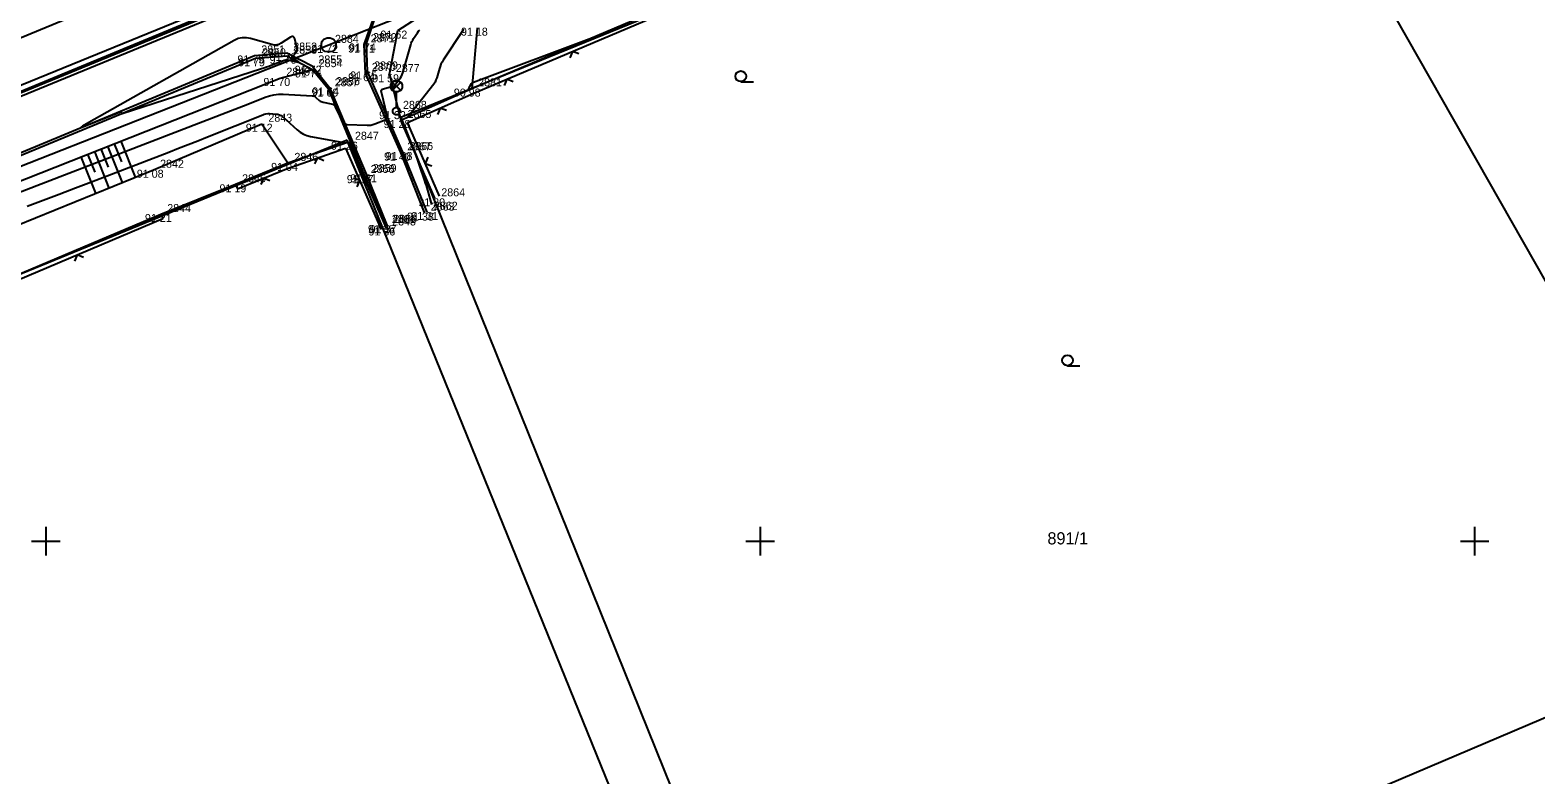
# Model space of a CAD drawing. Extents: x -711081 to -709338, y -1025122 to -1024092.
# Drawn here: x -710150.5 to -710097.9, y -1024708.2 to -1024682.1 of the extents above; entities that cross this region are included whole.
import ezdxf

# ---------------------------------------------------------------- set-up
doc = ezdxf.new("R2010")
doc.units = 0
for name, color, linetype in [('Ex_Major Contours', 7, 'Continuous'), ('Ex_Minor Contours', 7, 'Continuous'), ('Z_body', 7, 'Continuous'), ('Z_body_cisla', 7, 'Continuous'), ('Z_body_vysky_redukovane', 7, 'Continuous'), ('Z_chodnik', 7, 'Continuous'), ('Z_hektometricka_sit', 7, 'Continuous'), ('Z_hrany_paty', 7, 'Continuous'), ('Z_katastr_cisla_pozemkova', 7, 'Continuous'), ('Z_katastr_hranice', 7, 'Continuous'), ('Z_katastr_znacky_kultur', 7, 'Continuous'), ('Z_komunikace', 7, 'Continuous'), ('Z_obruba', 7, 'Continuous'), ('Z_ploty', 7, 'Continuous'), ('Z_ploty_znacky', 7, 'Continuous'), ('Z_site_kanalizace_znaky', 7, 'Continuous'), ('Z_site_vo_znaky', 7, 'Continuous'), ('Z_technicke_srafy', 7, 'Continuous'), ('Z_vdz12_plna', 7, 'Continuous'), ('Z_vdz25_plna', 7, 'Continuous'), ('Z_vstupy', 7, 'Continuous'), ('Z_znaky_kultur', 7, 'Continuous')]:
    doc.layers.add(name, color=color, linetype=linetype)

# ---------------------------------------------------------------- blocks, each defined once
blk = doc.blocks.new('POINT_DISPLAY')
blk.add_line((0, 0), (0, 0))
blk = doc.blocks.new('Z212')
for p, q in [((-0.17, 0.17), (0, 0)), ((0, 0), (0.17, 0.17))]:
    blk.add_line(p, q)
blk = doc.blocks.new('Z34')
for p, q in [((-0.15, 1.02), (-0.05, 1.07)), ((-0.05, 1.07), (0.05, 1.07)), ((0.05, 1.07), (0.15, 1.02)), ((-0.2, 0.93), (-0.15, 1.02)), ((-0.2, 0.82), (-0.2, 0.93)), ((-0.15, 0.72), (-0.2, 0.82)), ((0.15, 0.72), (-0.15, 1.02)), ((0.15, 1.02), (-0.15, 0.72)), ((-0.05, 0.68), (-0.15, 0.72)), ((0.05, 0.68), (-0.05, 0.68)), ((0, 0.13), (0, 0.68)), ((0.15, 0.72), (0.05, 0.68)), ((0.15, 1.02), (0.2, 0.93)), ((0.2, 0.82), (0.15, 0.72)), ((0.2, 0.93), (0.2, 0.82)), ((-0.13, 0.03), (-0.1, 0.08)), ((-0.13, -0.03), (-0.13, 0.03)), ((-0.1, 0.08), (-0.08, 0.1)), ((-0.08, 0.1), (-0.03, 0.13)), ((-0.03, 0.13), (0.03, 0.13)), ((0.03, 0.13), (0.08, 0.1)), ((0.08, 0.1), (0.1, 0.08)), ((0.1, 0.08), (0.13, 0.03)), ((0.13, 0.03), (0.13, -0.03)), ((-0.1, -0.08), (-0.13, -0.03)), ((-0.08, -0.1), (-0.1, -0.08)), ((-0.03, -0.13), (-0.08, -0.1)), ((0.03, -0.13), (-0.03, -0.13)), ((0.08, -0.1), (0.03, -0.13)), ((0.1, -0.08), (0.08, -0.1)), ((0.13, -0.03), (0.1, -0.08))]:
    blk.add_line(p, q)
blk = doc.blocks.new('Z620')
for p, q in [((-0.25, 0.05), (-0.23, 0.13)), ((-0.25, -0.05), (-0.25, 0.05)), ((-0.23, 0.13), (-0.17, 0.2)), ((-0.17, 0.2), (-0.05, 0.25)), ((-0.05, 0.25), (0.05, 0.25)), ((0.05, 0.25), (0.17, 0.2)), ((0.17, 0.2), (0.23, 0.13)), ((0.23, 0.13), (0.25, 0.05)), ((0.25, 0.05), (0.25, -0.05)), ((-0.2, -0.17), (-0.25, -0.05)), ((-0.13, -0.23), (-0.2, -0.17)), ((-0.05, -0.25), (-0.13, -0.23)), ((0.05, -0.25), (-0.05, -0.25)), ((0.13, -0.23), (0.05, -0.25)), ((0.2, -0.17), (0.13, -0.23)), ((0.25, -0.05), (0.2, -0.17))]:
    blk.add_line(p, q)
blk = doc.blocks.new('Z304')
blk.add_line((0, -0.19), (0.44, -0.19))
blk.add_circle((0, 0), 0.188)

msp = doc.modelspace()

# ---------------------------------------------------------------- linework, layer by layer
at = {"layer": 'Ex_Major Contours'}
msp.add_lwpolyline([(-710135.255, -1024684.233), (-710135.192, -1024684.153), (-710135.188, -1024684.148), (-710135.185, -1024684.143), (-710135.183, -1024684.138), (-710135.181, -1024684.132), (-710135.174, -1024684.108), (-710135.172, -1024684.103), (-710135.17, -1024684.097), (-710135.167, -1024684.092), (-710135.164, -1024684.086), (-710135.097, -1024683.984), (-710135.083, -1024683.967), (-710135.068, -1024683.952), (-710135.05, -1024683.94), (-710135.03, -1024683.931), (-710130.89, -1024682.38)], dxfattribs=at)
at = {"layer": 'Ex_Minor Contours'}
for points in [[(-710153.747, -1024688.868), (-710143.533, -1024684.942), (-710143.381, -1024684.884), (-710143.229, -1024684.824), (-710143.078, -1024684.765), (-710142.927, -1024684.705), (-710142.323, -1024684.463), (-710142.17, -1024684.411), (-710142.015, -1024684.376), (-710141.857, -1024684.359), (-710141.696, -1024684.359), (-710140.681, -1024684.412), (-710140.643, -1024684.417), (-710140.608, -1024684.428), (-710140.576, -1024684.445), (-710140.545, -1024684.468), (-710140.43, -1024684.572), (-710140.4, -1024684.596), (-710140.367, -1024684.615), (-710140.332, -1024684.629), (-710140.295, -1024684.638), (-710140.012, -1024684.689), (-710139.965, -1024684.703), (-710139.926, -1024684.726), (-710139.893, -1024684.758), (-710139.868, -1024684.8), (-710139.753, -1024685.047), (-710139.745, -1024685.062), (-710139.737, -1024685.078), (-710139.728, -1024685.093), (-710139.719, -1024685.107), (-710139.681, -1024685.165), (-710139.671, -1024685.18), (-710139.662, -1024685.195), (-710139.652, -1024685.209), (-710139.643, -1024685.224), (-710139.561, -1024685.356), (-710139.542, -1024685.38), (-710139.52, -1024685.397), (-710139.493, -1024685.408), (-710139.464, -1024685.413), (-710138.759, -1024685.444), (-710138.689, -1024685.443), (-710138.62, -1024685.435), (-710138.552, -1024685.42), (-710138.486, -1024685.398), (-710138.124, -1024685.254), (-710138.11, -1024685.247), (-710138.101, -1024685.236), (-710138.096, -1024685.223), (-710138.096, -1024685.208), (-710138.103, -1024685.12), (-710138.103, -1024685.115), (-710138.101, -1024685.111), (-710138.097, -1024685.11), (-710138.091, -1024685.111), (-710138.064, -1024685.122), (-710138.059, -1024685.123), (-710138.055, -1024685.122), (-710138.054, -1024685.119), (-710138.055, -1024685.113), (-710138.257, -1024684.29), (-710138.261, -1024684.245), (-710138.25, -1024684.21), (-710138.224, -1024684.184), (-710138.183, -1024684.166), (-710137.902, -1024684.093), (-710137.896, -1024684.092), (-710137.891, -1024684.093), (-710137.886, -1024684.095), (-710137.881, -1024684.099), (-710137.863, -1024684.116), (-710137.858, -1024684.119), (-710137.854, -1024684.12), (-710137.85, -1024684.118), (-710137.846, -1024684.115), (-710137.622, -1024683.831), (-710137.586, -1024683.781), (-710137.556, -1024683.728), (-710137.531, -1024683.673), (-710137.511, -1024683.614), (-710137.228, -1024682.628), (-710137.209, -1024682.57), (-710137.186, -1024682.515), (-710137.159, -1024682.461), (-710137.127, -1024682.409), (-710136.992, -1024682.205), (-710136.956, -1024682.156), (-710136.915, -1024682.113)], [(-710135.376, -1024682.09), (-710135.406, -1024682.13), (-710136.092, -1024683.166), (-710136.134, -1024683.236), (-710136.171, -1024683.309), (-710136.203, -1024683.384), (-710136.228, -1024683.462), (-710136.319, -1024683.78), (-710136.346, -1024683.857), (-710136.379, -1024683.931), (-710136.42, -1024684.002), (-710136.467, -1024684.068), (-710137.322, -1024685.15)], [(-710150.656, -1024688.277), (-710150.091, -1024688.064), (-710149.526, -1024687.851), (-710148.961, -1024687.636), (-710148.398, -1024687.42), (-710145.699, -1024686.383), (-710145.357, -1024686.251), (-710145.016, -1024686.117), (-710144.676, -1024685.983), (-710144.336, -1024685.848), (-710142.409, -1024685.076), (-710142.352, -1024685.057), (-710142.294, -1024685.044), (-710142.235, -1024685.038), (-710142.175, -1024685.038), (-710141.933, -1024685.051), (-710141.874, -1024685.058), (-710141.819, -1024685.076), (-710141.768, -1024685.102), (-710141.721, -1024685.138), (-710141.204, -1024685.603), (-710141.098, -1024685.686), (-710140.985, -1024685.752), (-710140.863, -1024685.801), (-710140.733, -1024685.833), (-710139.506, -1024686.054)], [(-710137.124, -1024686.288), (-710136.747, -1024687.386), (-710136.72, -1024687.468), (-710136.693, -1024687.551), (-710136.668, -1024687.634), (-710136.644, -1024687.717), (-710136.503, -1024688.218)]]:
    msp.add_lwpolyline(points, dxfattribs=at)
msp.add_lwpolyline([(-710141.842, -1024682.613), (-710141.92, -1024682.634), (-710142.002, -1024682.636), (-710142.086, -1024682.621), (-710142.83, -1024682.408), (-710142.98, -1024682.379), (-710143.127, -1024682.381), (-710143.271, -1024682.413), (-710143.411, -1024682.476), (-710148.58, -1024685.39), (-710148.718, -1024685.472), (-710148.76, -1024685.508), (-710148.706, -1024685.498), (-710148.555, -1024685.442), (-710147.379, -1024684.973), (-710147.372, -1024684.971), (-710147.366, -1024684.972), (-710147.362, -1024684.976), (-710147.358, -1024684.983), (-710147.348, -1024685.017), (-710147.345, -1024685.024), (-710147.34, -1024685.028), (-710147.334, -1024685.029), (-710147.327, -1024685.028), (-710142.451, -1024683.462), (-710142.365, -1024683.434), (-710142.279, -1024683.404), (-710142.193, -1024683.373), (-710142.108, -1024683.34), (-710141.716, -1024683.186), (-710141.658, -1024683.167), (-710141.599, -1024683.158), (-710141.539, -1024683.158), (-710141.479, -1024683.168), (-710141.181, -1024683.235), (-710141.156, -1024683.239), (-710141.146, -1024683.237), (-710141.151, -1024683.228), (-710141.171, -1024683.212), (-710141.324, -1024683.108), (-710141.331, -1024683.102), (-710141.336, -1024683.095), (-710141.339, -1024683.088), (-710141.34, -1024683.079), (-710141.34, -1024683.041), (-710141.339, -1024683.032), (-710141.337, -1024683.024), (-710141.333, -1024683.015), (-710141.328, -1024683.008), (-710141.231, -1024682.886), (-710141.216, -1024682.862), (-710141.207, -1024682.837), (-710141.204, -1024682.811), (-710141.208, -1024682.783), (-710141.286, -1024682.425), (-710141.307, -1024682.369), (-710141.339, -1024682.34), (-710141.382, -1024682.338), (-710141.436, -1024682.363), (-710141.765, -1024682.574)], close=True, dxfattribs=at)
at = {"layer": 'Z_chodnik'}
for p, q in [((-710138.86, -1024682.62), (-710138.51, -1024681.65)), ((-710138.81, -1024683.62), (-710138.86, -1024682.62)), ((-710156.78, -1024688.85), (-710142.69, -1024683)), ((-710142.69, -1024683), (-710141.56, -1024682.91)), ((-710141.56, -1024682.91), (-710140.68, -1024683.36)), ((-710140.68, -1024683.36), (-710140.07, -1024684.12)), ((-710137.58, -1024686.4), (-710138.81, -1024683.62)), ((-710140.07, -1024684.12), (-710138.79, -1024687.16)), ((-710136.75, -1024688.5), (-710137.58, -1024686.4)), ((-710138.79, -1024687.16), (-710138.06, -1024688.94))]:
    msp.add_line(p, q, dxfattribs=at)
at = {"layer": 'Z_hektometricka_sit'}
for p, q in [((-710150, -1024699.5), (-710150, -1024700.5)), ((-710125, -1024699.5), (-710125, -1024700.5)), ((-710100, -1024699.5), (-710100, -1024700.5)), ((-710150.5, -1024700), (-710149.5, -1024700)), ((-710125.5, -1024700), (-710124.5, -1024700)), ((-710100.5, -1024700), (-710099.5, -1024700))]:
    msp.add_line(p, q, dxfattribs=at)
at = {"layer": 'Z_hrany_paty'}
for p, q in [((-710137.68, -1024682.13), (-710135.55, -1024680.75)), ((-710137.97, -1024683.66), (-710137.68, -1024682.13)), ((-710134.91, -1024682.03), (-710135.09, -1024684.16)), ((-710156.89, -1024689.76), (-710141.8, -1024683.79)), ((-710141.8, -1024683.79), (-710140.67, -1024683.49)), ((-710137.97, -1024683.66), (-710137.57, -1024685.26)), ((-710146.23, -1024687), (-710142.44, -1024685.39)), ((-710142.44, -1024685.39), (-710141.53, -1024686.76)), ((-710156.79, -1024691.29), (-710146.23, -1024687))]:
    msp.add_line(p, q, dxfattribs=at)
at = {"layer": 'Z_katastr_hranice'}
for p, q in [((-710109.15, -1024670.43), (-710154.63, -1024688.37)), ((-710107.7, -1024672.99), (-710137.58, -1024685.17)), ((-710090.53, -1024703.19), (-710107.7, -1024672.99)), ((-710173.64, -1024693.67), (-710138.49, -1024679.21)), ((-710137.58, -1024685.17), (-710124.48, -1024717.61)), ((-710139.45, -1024685.96), (-710170.96, -1024698.88)), ((-710124.33, -1024723.2), (-710139.45, -1024685.96)), ((-710124.48, -1024717.61), (-710090.53, -1024703.19))]:
    msp.add_line(p, q, dxfattribs=at)
at = {"layer": 'Z_katastr_znacky_kultur'}
msp.add_line((-710114.248, -1024693.86), (-710113.811, -1024693.86), dxfattribs=at)
msp.add_circle((-710114.248, -1024693.672), 0.187, dxfattribs=at)
at = {"layer": 'Z_komunikace'}
msp.add_line((-710157.66, -1024687.05), (-710143.73, -1024681.3), dxfattribs=at)
at = {"layer": 'Z_obruba'}
for p, q in [((-710157.54, -1024687.16), (-710143.69, -1024681.47)), ((-710138.78, -1024682.58), (-710138.49, -1024681.71)), ((-710138.74, -1024683.56), (-710138.78, -1024682.58)), ((-710156.71, -1024688.9), (-710142.66, -1024683.1)), ((-710142.66, -1024683.1), (-710141.56, -1024683.01)), ((-710141.56, -1024683.01), (-710140.67, -1024683.49)), ((-710140.67, -1024683.49), (-710140.12, -1024684.16)), ((-710137.5, -1024686.38), (-710138.74, -1024683.56)), ((-710140.12, -1024684.16), (-710138.86, -1024687.19)), ((-710136.65, -1024688.48), (-710137.5, -1024686.38)), ((-710138.86, -1024687.19), (-710138.12, -1024688.94))]:
    msp.add_line(p, q, dxfattribs=at)
at = {"layer": 'Z_ploty'}
for p, q in [((-710135.09, -1024684.16), (-710126.69, -1024680.6)), ((-710135.02, -1024684.32), (-710126.62, -1024680.76)), ((-710137.57, -1024685.26), (-710135.09, -1024684.16)), ((-710137.34, -1024685.35), (-710135.02, -1024684.32)), ((-710136.38, -1024688), (-710137.57, -1024685.26)), ((-710136.22, -1024687.93), (-710137.34, -1024685.35)), ((-710141.53, -1024686.76), (-710139.41, -1024686.02)), ((-710141.47, -1024686.93), (-710139.51, -1024686.24)), ((-710139.51, -1024686.24), (-710138.26, -1024689.09)), ((-710139.41, -1024686.02), (-710138.1, -1024689.02)), ((-710143.36, -1024687.51), (-710141.53, -1024686.76)), ((-710143.29, -1024687.67), (-710141.46, -1024686.92)), ((-710143.36, -1024687.51), (-710143.29, -1024687.67)), ((-710170.84, -1024699.08), (-710145.97, -1024688.55)), ((-710170.77, -1024699.24), (-710145.9, -1024688.71)), ((-710145.97, -1024688.55), (-710145.9, -1024688.71))]:
    msp.add_line(p, q, dxfattribs=at)
at = {"layer": 'Z_technicke_srafy'}
for p, q in [((-710148.3, -1024686.36), (-710147.79, -1024687.64)), ((-710148.07, -1024686.27), (-710147.82, -1024686.91)), ((-710147.84, -1024686.18), (-710147.33, -1024687.45)), ((-710147.61, -1024686.09), (-710147.35, -1024686.72)), ((-710147.37, -1024686), (-710146.87, -1024687.26)), ((-710148.77, -1024686.55), (-710148.26, -1024687.82)), ((-710148.54, -1024686.46), (-710148.28, -1024687.09))]:
    msp.add_line(p, q, dxfattribs=at)
at = {"layer": 'Z_vdz12_plna'}
msp.add_line((-710157.61, -1024686.78), (-710143.76, -1024681.14), dxfattribs=at)
at = {"layer": 'Z_vdz25_plna'}
msp.add_line((-710158.2, -1024685.41), (-710144.27, -1024679.64), dxfattribs=at)
at = {"layer": 'Z_vstupy'}
msp.add_line((-710145.97, -1024688.55), (-710143.36, -1024687.51), dxfattribs=at)

# ---------------------------------------------------------------- block references
at = {"layer": 'Z_body'}
for p in [(-710137.68, -1024682.13), (-710140.1, -1024682.63), (-710138.86, -1024682.62), (-710138.78, -1024682.58), (-710142.69, -1024683), (-710142.66, -1024683.1), (-710141.56, -1024682.91), (-710141.56, -1024683.01), (-710141.8, -1024683.79), (-710140.68, -1024683.36), (-710140.67, -1024683.49), (-710138.81, -1024683.62), (-710138.74, -1024683.56), (-710137.97, -1024683.66), (-710140.12, -1024684.16), (-710140.07, -1024684.12), (-710135.09, -1024684.16), (-710137.73, -1024684.95), (-710137.57, -1024685.26), (-710142.44, -1024685.39), (-710139.41, -1024686.02), (-710137.58, -1024686.4), (-710137.5, -1024686.38), (-710141.53, -1024686.76), (-710146.23, -1024687), (-710138.86, -1024687.19), (-710138.79, -1024687.16), (-710143.36, -1024687.51), (-710136.38, -1024688), (-710136.75, -1024688.5), (-710136.65, -1024688.48), (-710145.97, -1024688.55), (-710138.12, -1024688.94), (-710138.1, -1024689.02), (-710138.06, -1024688.94)]:
    msp.add_blockref('POINT_DISPLAY', p, dxfattribs=at)
at = {"layer": 'Z_ploty_znacky'}
for p, rotation in [((-710131.57, -1024682.86), -157), ((-710133.87, -1024683.83), -157), ((-710136.2, -1024684.84), -156.10000000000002), ((-710140.49, -1024686.58), -160.8), ((-710136.72, -1024686.78), -66.5), ((-710142.38, -1024687.3), -157.7), ((-710139.01, -1024687.38), 113.6), ((-710148.9, -1024689.98), -157.10000000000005)]:
    msp.add_blockref('Z212', p, dxfattribs=dict(at, rotation=rotation))
at = {"layer": 'Z_site_kanalizace_znaky'}
msp.add_blockref('Z620', (-710140.1, -1024682.63), dxfattribs=at)
at = {"layer": 'Z_site_vo_znaky'}
msp.add_blockref('Z34', (-710137.73, -1024684.95), dxfattribs=at)
at = {"layer": 'Z_znaky_kultur'}
msp.add_blockref('Z304', (-710125.68, -1024683.73), dxfattribs=at)

# ---------------------------------------------------------------- texts
at = {"layer": 'Z_body_cisla'}
for s, p in [('2851', (-710142.46, -1024682.93)), ('2852', (-710141.34, -1024682.83)), ('2853', (-710141.34, -1024682.94)), ('2884', (-710139.88, -1024682.56)), ('2871', (-710138.63, -1024682.54)), ('2872', (-710138.55, -1024682.5)), ('2850', (-710142.43, -1024683.03)), ('2855', (-710140.46, -1024683.28)), ('2854', (-710140.45, -1024683.41)), ('2870', (-710138.59, -1024683.54)), ('2869', (-710138.51, -1024683.49)), ('2849', (-710141.58, -1024683.71)), ('2856', (-710139.84, -1024684.04)), ('2877', (-710137.75, -1024683.58)), ('2857', (-710139.89, -1024684.08)), ('2881', (-710134.87, -1024684.08)), ('2868', (-710137.5, -1024684.87)), ('2843', (-710142.21, -1024685.32)), ('2865', (-710137.34, -1024685.19)), ('2847', (-710139.18, -1024685.95)), ('2846', (-710141.3, -1024686.69)), ('2867', (-710137.35, -1024686.32)), ('2866', (-710137.28, -1024686.31)), ('2842', (-710146, -1024686.93)), ('2858', (-710138.63, -1024687.11)), ('2859', (-710138.56, -1024687.08)), ('2845', (-710143.13, -1024687.44)), ('2864', (-710136.16, -1024687.93)), ('2844', (-710145.75, -1024688.48)), ('2863', (-710136.53, -1024688.43)), ('2862', (-710136.42, -1024688.4)), ('2861', (-710137.89, -1024688.86)), ('2848', (-710137.88, -1024688.95)), ('2860', (-710137.84, -1024688.86))]:
    msp.add_text(s, height=0.28, dxfattribs=at).set_placement(p)
at = {"layer": 'Z_body_vysky_redukovane'}
for s, p in [('91 62', (-710138.287, -1024682.41)), ('91 18', (-710135.47, -1024682.31)), ('91 72', (-710140.707, -1024682.91)), ('91 71', (-710139.42, -1024682.9)), ('91 74', (-710139.387, -1024682.86)), ('91 79', (-710143.297, -1024683.28)), ('91 79', (-710143.267, -1024683.38)), ('91 76', (-710142.167, -1024683.19)), ('91 76', (-710142.167, -1024683.29)), ('91 70', (-710142.383, -1024684.07)), ('91 72', (-710141.287, -1024683.64)), ('91 74', (-710141.277, -1024683.77)), ('91 64', (-710139.417, -1024683.9)), ('91 65', (-710139.347, -1024683.84)), ('91 59', (-710138.577, -1024683.94)), ('91 60', (-710140.703, -1024684.44)), ('91 64', (-710140.677, -1024684.4)), ('90 98', (-710135.72, -1024684.44)), ('91 32', (-710138.337, -1024685.23)), ('91 28', (-710138.177, -1024685.54)), ('91 12', (-710143, -1024685.67)), ('91 26', (-710140.017, -1024686.3)), ('91 40', (-710138.163, -1024686.68)), ('91 38', (-710138.107, -1024686.66)), ('91 04', (-710142.113, -1024687.04)), ('91 08', (-710146.813, -1024687.28)), ('91 27', (-710139.467, -1024687.47)), ('91 31', (-710139.35, -1024687.44)), ('91 19', (-710143.92, -1024687.79)), ('91 20', (-710136.963, -1024688.28)), ('91 38', (-710137.357, -1024688.78)), ('91 31', (-710137.21, -1024688.76)), ('91 21', (-710146.53, -1024688.83)), ('91 35', (-710138.727, -1024689.22)), ('91 36', (-710138.707, -1024689.3)), ('91 37', (-710138.667, -1024689.22))]:
    msp.add_text(s, height=0.28, dxfattribs=at).set_placement(p)
at = {"layer": 'Z_katastr_cisla_pozemkova'}
msp.add_text('891/1', height=0.425, dxfattribs=at).set_placement((-710114.95, -1024700.11))

doc.saveas('drawing.dxf')
